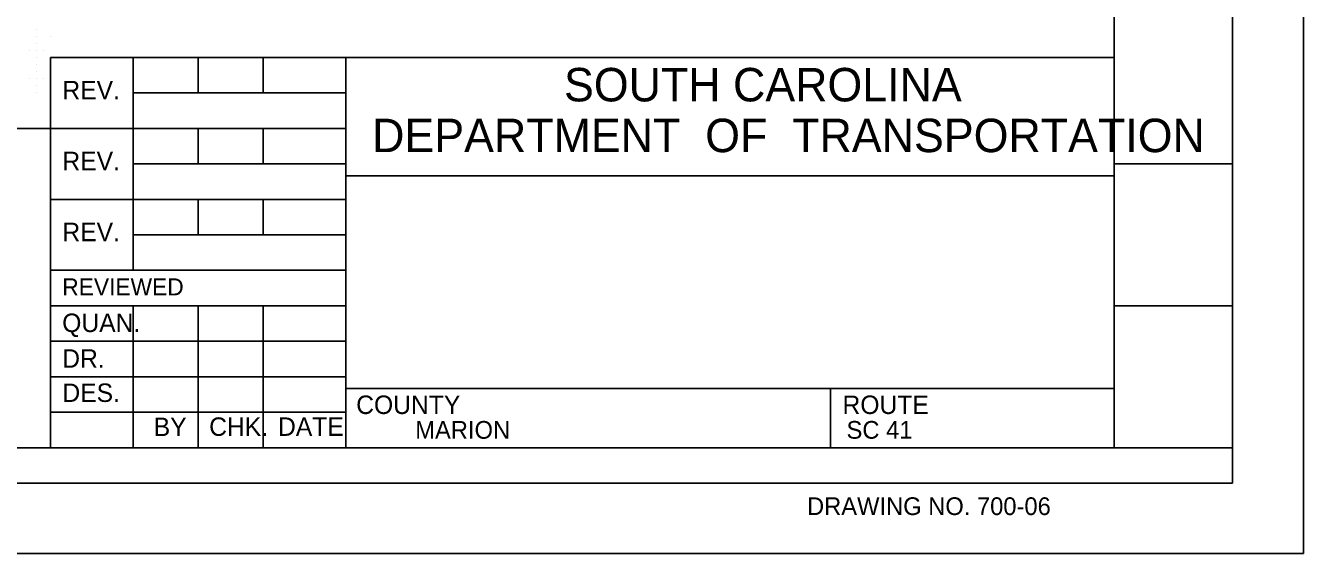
# Model space of a CAD drawing. Extents: x -0.04 to 4.87, y 0 to 1.83.
# Drawn here: x 2.214 to 2.964, y 0 to 0.31 of the extents above; entities that cross this region are included whole.
import ezdxf

# ---------------------------------------------------------------- set-up
doc = ezdxf.new("R2010")
doc.units = 0
for name, color, linetype in [('BR_BORDER LINES', 7, 'Continuous'), ('BR_GRID DOTS', 7, 'Continuous'), ('BR_GRID LINES', 7, 'Continuous'), ('BR_TEXT', 7, 'Continuous'), ('RD_SHT_IplotShp', 7, 'Continuous')]:
    doc.layers.add(name, color=color, linetype=linetype)

msp = doc.modelspace()

# ---------------------------------------------------------------- linework, layer by layer
at = {"layer": 'BR_BORDER LINES'}
for p, q in [((2.92272, 0.04127), (2.92272, 1.79153)), ((2.85328, 0.89543), (2.85328, 0.29544)), ((2.85328, 0.29544), (2.85328, 0.09683)), ((2.22828, 0.0621), (2.22828, 0.29127)), ((2.22828, 0.29127), (2.85328, 0.29127)), ((2.27689, 0.29127), (2.27689, 0.16627)), ((2.31509, 0.27044), (2.31509, 0.29127)), ((2.35328, 0.27044), (2.35328, 0.29127)), ((2.40189, 0.0621), (2.40189, 0.29127)), ((2.27689, 0.27044), (2.40189, 0.27044)), ((2.03557, 0.2496), (2.22828, 0.2496)), ((2.22828, 0.2496), (2.40189, 0.2496)), ((2.31509, 0.22877), (2.31509, 0.2496)), ((2.35328, 0.22877), (2.35328, 0.2496)), ((2.27689, 0.22877), (2.40189, 0.22877)), ((2.40189, 0.22183), (2.85328, 0.22183)), ((2.40189, 0.22183), (2.40189, 0.22183)), ((2.85328, 0.22183), (2.85328, 0.22183)), ((2.22828, 0.20794), (2.40189, 0.20794)), ((2.31509, 0.1871), (2.31509, 0.20794)), ((2.35328, 0.1871), (2.35328, 0.20794)), ((2.27689, 0.1871), (2.40189, 0.1871)), ((2.22828, 0.16627), (2.40189, 0.16627)), ((2.22828, 0.14544), (2.40189, 0.14544)), ((2.27689, 0.14544), (2.27689, 0.0621)), ((2.31509, 0.14544), (2.31509, 0.0621)), ((2.35328, 0.14544), (2.35328, 0.0621)), ((2.22828, 0.1246), (2.40189, 0.1246)), ((2.22828, 0.10377), (2.40189, 0.10377)), ((2.40189, 0.09683), (2.85328, 0.09683)), ((2.68662, 0.0621), (2.68662, 0.09683)), ((2.85328, 0.0621), (2.85328, 0.09683)), ((2.22828, 0.08294), (2.40189, 0.08294)), ((0.18664, 0.0621), (2.22829, 0.0621)), ((2.85328, 0.0621), (2.22829, 0.0621)), ((0.1172, 0.04127), (2.92272, 0.04127)), ((-0.03561, 0), (2.96439, 0))]:
    msp.add_line(p, q, dxfattribs=at)
at = {"layer": 'BR_GRID DOTS'}
for p, q in [((2.21996, 0.30794), (2.21996, 0.30794)), ((2.21996, 0.30377), (2.21996, 0.30377)), ((2.22829, 0.30377), (2.22829, 0.30377)), ((2.21579, 0.29544), (2.21579, 0.29544)), ((2.21996, 0.2996), (2.21996, 0.2996)), ((2.21996, 0.2996), (2.21996, 0.2996)), ((2.21996, 0.29544), (2.21996, 0.29544)), ((2.22412, 0.29544), (2.22412, 0.29544)), ((2.21996, 0.29127), (2.21996, 0.29127)), ((2.21996, 0.2871), (2.21996, 0.2871)), ((2.21579, 0.27877), (2.21579, 0.27877)), ((2.21996, 0.28294), (2.21996, 0.28294)), ((2.21996, 0.27877), (2.21996, 0.27877)), ((2.22412, 0.27877), (2.22412, 0.27877)), ((2.21996, 0.2746), (2.21996, 0.2746)), ((2.21996, 0.27044), (2.21996, 0.27044))]:
    msp.add_line(p, q, dxfattribs=at)
at = {"layer": 'BR_GRID LINES'}
for p, q in [((2.85328, 0.22877), (2.92272, 0.22877)), ((2.85328, 0.14544), (2.92272, 0.14544)), ((2.85328, 0.0621), (2.92272, 0.0621))]:
    msp.add_line(p, q, dxfattribs=at)
at = {"layer": 'RD_SHT_IplotShp'}
msp.add_lwpolyline([(-0.03561, 0), (2.96439, 0), (2.96439, 1.83333), (-0.03561, 1.83333)], close=True, dxfattribs=at)

# ---------------------------------------------------------------- texts
at = {"layer": 'BR_TEXT'}
for s, height, p in [('SOUTH CAROLINA', 0.0196543, (2.53001, 0.26548)), ('REV.', 0.010833, (2.23534, 0.26672)), ('DEPARTMENT  OF  TRANSPORTATION', 0.0196543, (2.41729, 0.23567)), ('REV.', 0.010833, (2.23534, 0.22506)), ('REV.', 0.010833, (2.23534, 0.18339)), ('REVIEWED', 0.01, (2.23528, 0.15156)), ('QUAN.', 0.010833, (2.23523, 0.13003)), ('DR.', 0.010833, (2.23525, 0.10907)), ('DES.', 0.010833, (2.23534, 0.08897)), ('COUNTY', 0.010833, (2.40794, 0.0819)), ('ROUTE', 0.010833, (2.69362, 0.0819)), ('BY', 0.010833, (2.289, 0.06894)), ('CHK.', 0.010833, (2.32157, 0.06905)), ('DATE', 0.010833, (2.36201, 0.06906)), ('MARION', 0.010417, (2.44263, 0.06736)), ('SC 41', 0.010417, (2.69599, 0.06736)), ('DRAWING NO. 700-06', 0.0104167, (2.67278, 0.02254))]:
    msp.add_text(s, height=height, dxfattribs=at).set_placement(p)

doc.saveas('drawing.dxf')
